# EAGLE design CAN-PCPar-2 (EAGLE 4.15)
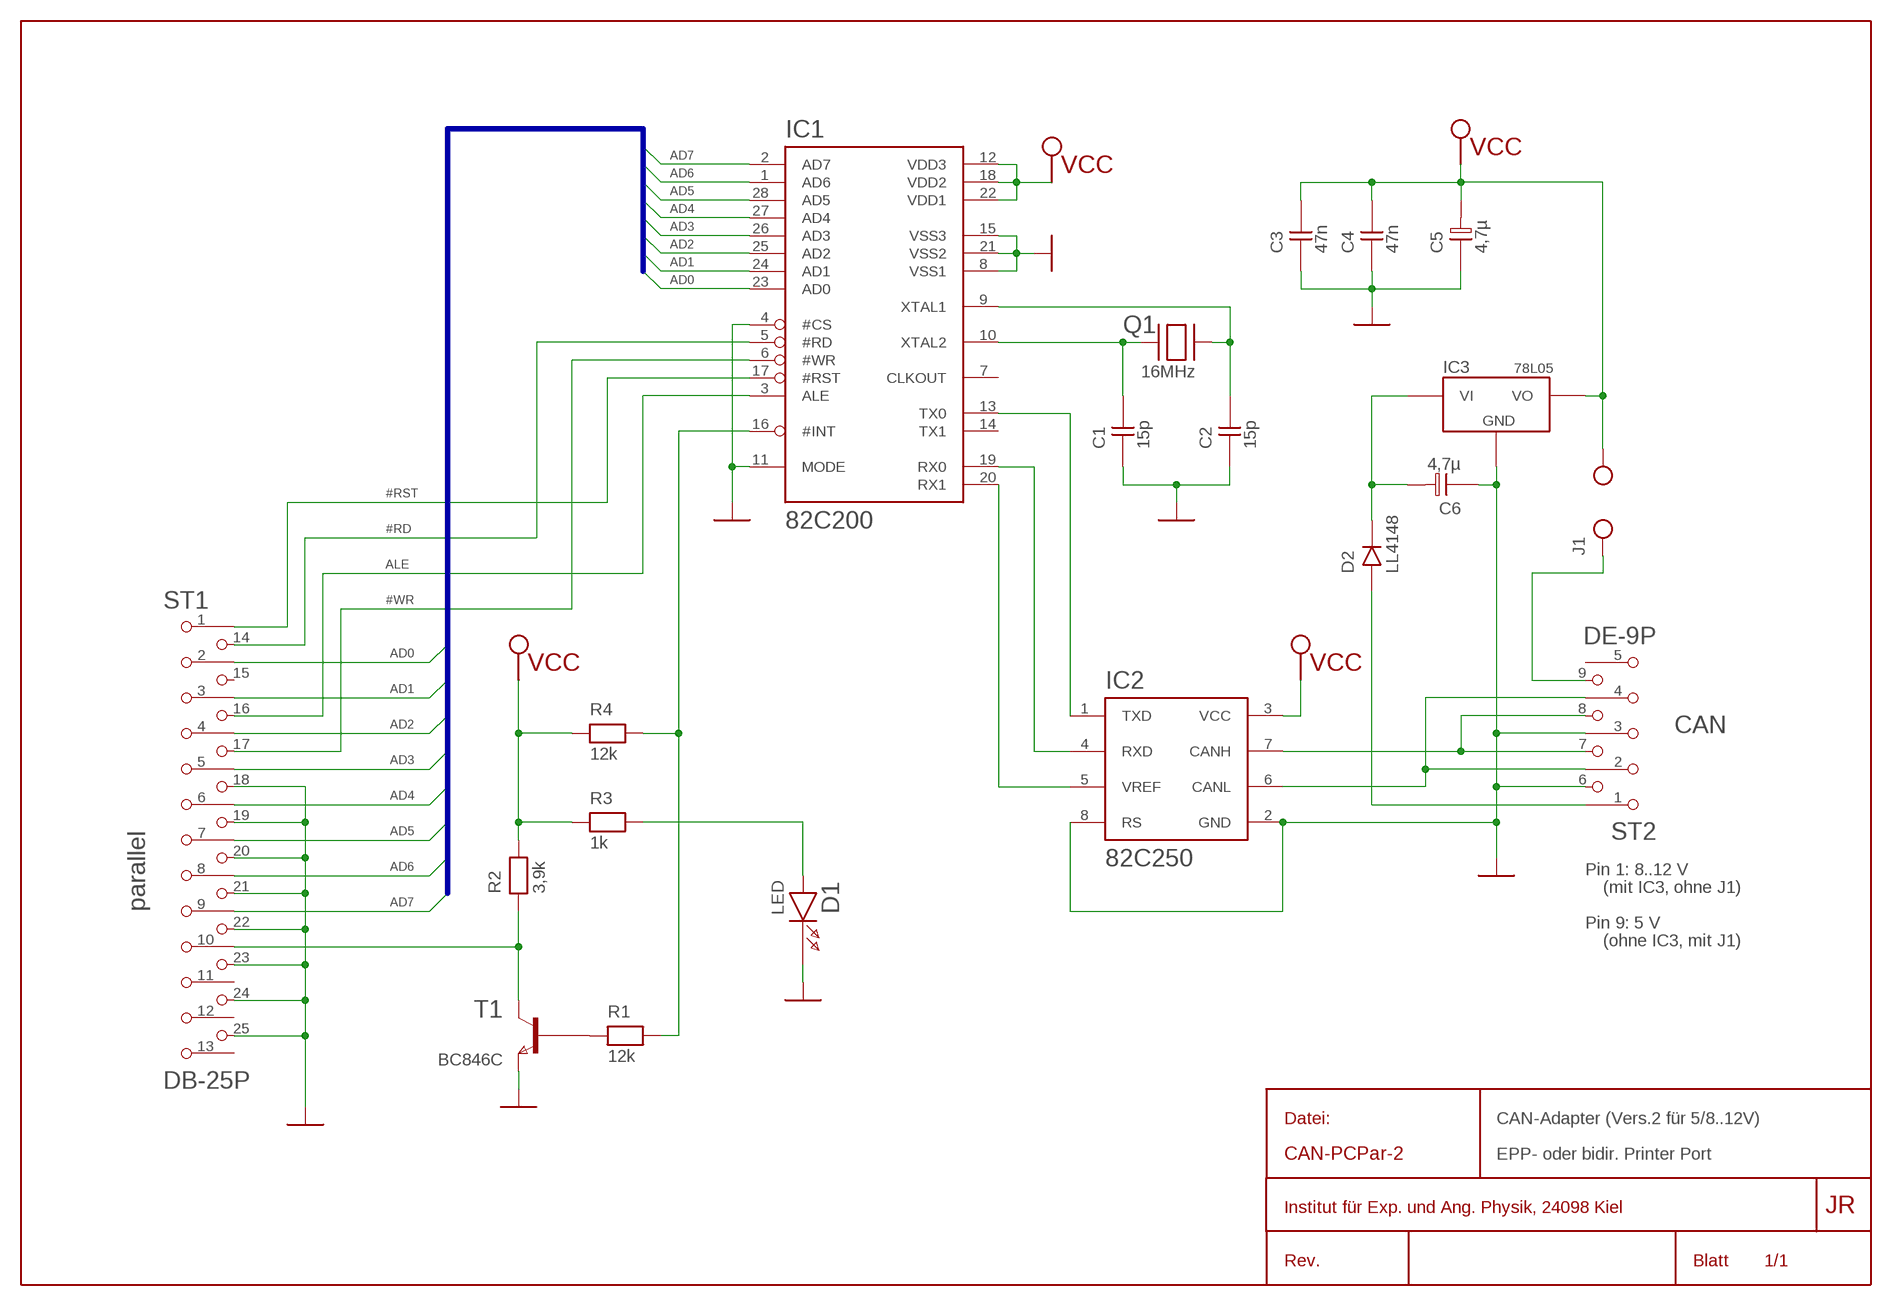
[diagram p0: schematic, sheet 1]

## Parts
C1  15p  CAP01  [C-1206]
C2  15p  CAP01  [C-1206]
C3  47n  CAP02  [C-1206]
C4  47n  CAP02  [C-1206]
C5  4,7µ  ELKOS-3528-B  [E-3528]
C6  4,7µ  ELKOS-3528-B  [E-3528]
D1  LED  [XLED3]
D2  LL4148  D-SOD80  [SOD-80]
IC1  82C200  [SO-28L]
IC2  82C250  [SO-8]
IC3  78L05  78XXTO92-DLH  [XTO92H]
J1  JUMPERSMD  [1206]
Q1  16MHz  QUARZ-V  [XQV]
R1  12k  RES04  [1206]
R2  3,9k  RES04  [1206]
R3  1k  RES04  [1206]
R4  12k  RES03  [1206]
ST1  DB-25P  [D-25ME]
ST2  DE-9P  [D-09ME]
T1  BC846C  NPN-EBC-42  [SOT-23]

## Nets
#RD: IC1.5(#RD) ST1.14
#RST: IC1.17(#RST) ST1.1
#WR: IC1.6(#WR) ST1.17
AD0: IC1.23(AD0) ST1.2
AD1: IC1.24(AD1) ST1.3
AD2: IC1.25(AD2) ST1.4
AD3: IC1.26(AD3) ST1.5
AD4: IC1.27(AD4) ST1.6
AD5: IC1.28(AD5) ST1.7
AD6: IC1.1(AD6) ST1.8
AD7: IC1.2(AD7) ST1.9
ALE: IC1.3(ALE) ST1.16
GND: C1.1 C2.1 C3.1 C4.1 C5.N C6.N D1.K IC1.4(#CS) IC1.8(VSS1) IC1.11(MODE) IC1.15(VSS3) IC1.21(VSS2) IC2.2(GND) IC2.8(RS) IC3.2(GND) ST1.18 ST1.19 ST1.20 ST1.21 ST1.22 ST1.23 ST1.24 ST1.25 ST2.3 ST2.6 T1.1(E)
N$1: C1.2 IC1.10(XTAL2) Q1.1
N$2: C2.2 IC1.9(XTAL1) Q1.2
N$3: R1.1 T1.2(B)
N$4: IC1.16(#INT) R1.2 R4.2
N$5: D1.A R3.2
N$6: J1.1 ST2.9
N$7: C6.P D2.2(K) IC3.3(VI)
N$8: D2.1(A) ST2.1
N$14: IC2.6(CANL) ST2.2 ST2.4
N$16: IC2.7(CANH) ST2.7 ST2.8
N$19: IC1.13(TX0) IC2.1(TXD)
N$20: IC1.19(RX0) IC2.4(RXD)
N$21: IC1.20(RX1) IC2.5(VREF)
N$26: R2.1 ST1.10 T1.3(C)
VCC: C3.2 C4.2 C5.P IC1.12(VDD3) IC1.18(VDD2) IC1.22(VDD1) IC2.3(VCC) IC3.1(VO) J1.2 R2.2 R3.1 R4.1
Unconnected: IC1.7(CLKOUT) IC1.14(TX1) ST1.11 ST1.12 ST1.13 ST1.15 ST2.5

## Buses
AD[0..7]

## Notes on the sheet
- CAN
- Pin 1: 8..12 V
- (mit IC3, ohne J1)
- parallel
- Pin 9: 5 V
- (ohne IC3, mit J1)
- CAN-Adapter (Vers.2 für 5/8..12V)
- EPP- oder bidir. Printer Port

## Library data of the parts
C1 C2 = IAP:CAP01
C3 C4 = IAP:CAP02
C5 C6 = JR:ELKO
D1 = JR:LED
D2 = JR-SMD:D-SOD80
IC1 = CAN:82C200
IC2 = CAN:82C250
IC3 = JR:78XX
J1 = mc-parts:JUMPER: Jumper
Q1 = IAP:QUARZ-V
R1 R2 = IAP:RES04
R3 = JR:RES04
R4 = JR:RES03
ST1 = STECKER:DB-25P
ST2 = STECKER:DE-9P
T1 = IAP:NPN-EBC-42

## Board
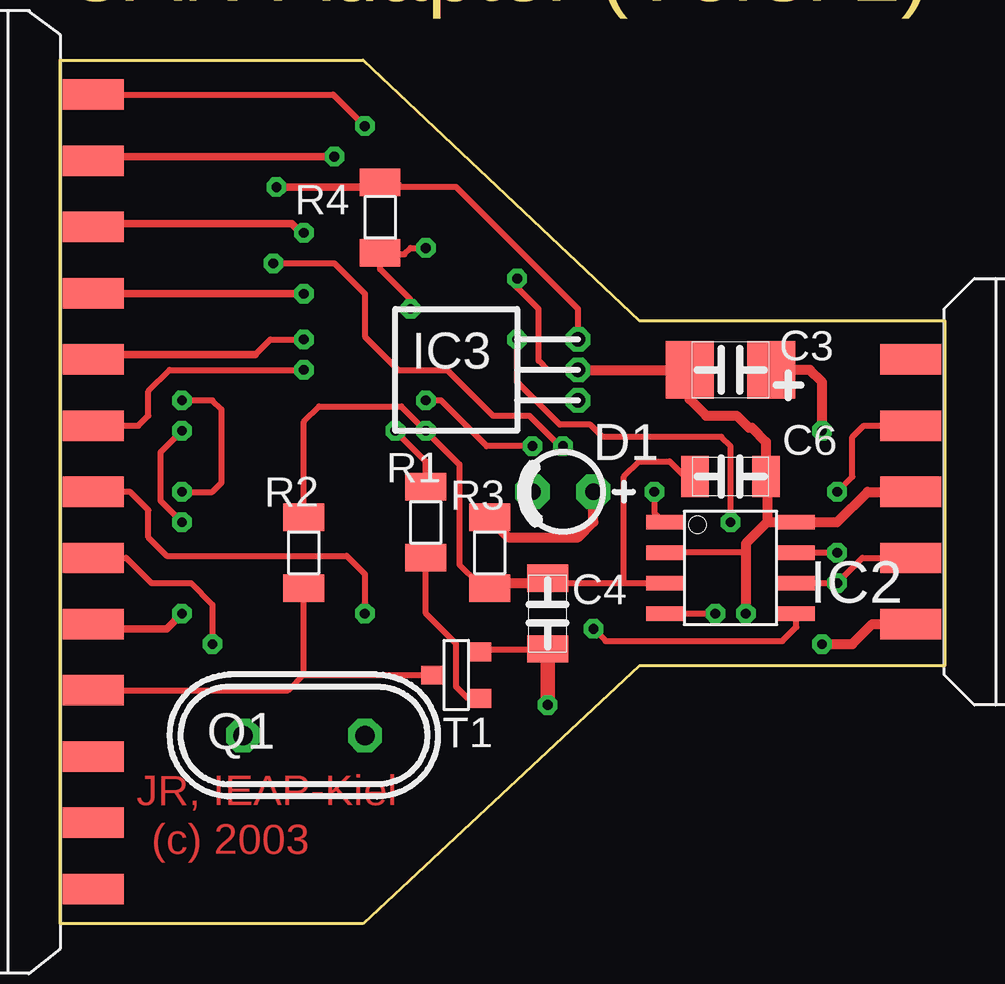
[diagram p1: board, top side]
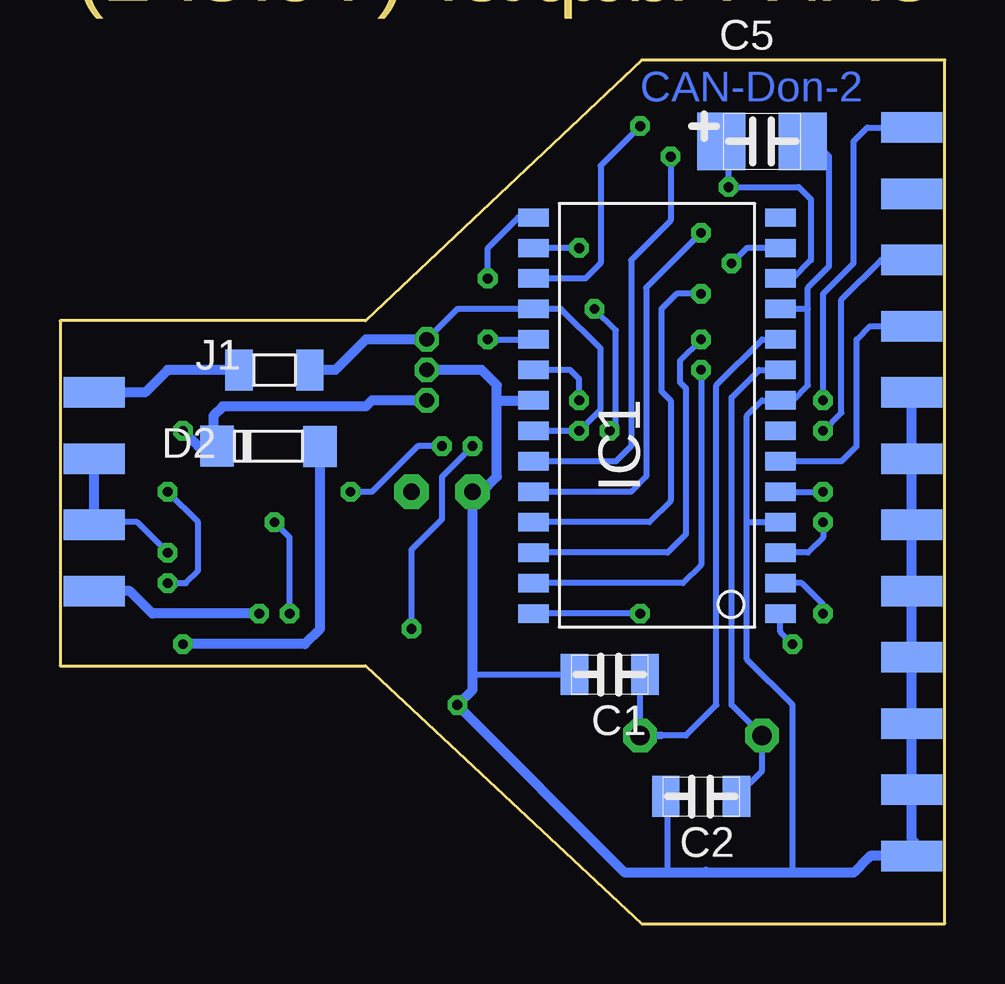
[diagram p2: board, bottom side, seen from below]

Size 36.87 x 36 mm. Coordinates in mm from the lower left corner, seen from the top.
Outline: 0,36 12.63,36 24.14,25.13 36.87,25.13 36.87,10.75 24.14,10.75 12.63,0 0,0 0,36
Copper layers (1*16): Top 0.035mm / dielectric 1.5mm / Bottom 0.035mm
Design rules "Standard": minimum track width 10mil, minimum drill 16mil, track to track 8mil, track to pad 8mil, pad to pad 8mil, via to via 8mil, smd to smd 8mil, copper to edge 0mil, drill to drill 8mil, minimum pad ring 8mil, minimum via ring 8mil, stop-mask expansion 4mil, vias tented up to drill 0mil, thermal gap 10mil

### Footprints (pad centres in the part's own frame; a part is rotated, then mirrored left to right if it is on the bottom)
C-1206 = smd 1.143 x 1.702: 1 -1.473,0; 2 1.473,0
E-3528 = smd 2.007 x 2.388: N 1.702,0; P -1.702,0
XLED3 = drill 0.7 pad 1.422 octagon: A 1.905,0; K -0.635,0
SOD-80 = smd 1.397 x 1.702: 1 1.905,-0.025; 2 -2.388,0
SO-28L = smd 0.762 x 1.27: 1 -7.62,-5.207; 2 -6.35,-5.207; 3 -5.08,-5.207; 4 -3.81,-5.207; 5 -2.54,-5.207; 6 -1.27,-5.207; 7 0,-5.207; 8 1.27,-5.207; 9 2.54,-5.207; 10 3.81,-5.207; 11 5.08,-5.207; 12 6.35,-5.207; 13 7.62,-5.207; 14 8.89,-5.207; 15 8.89,5.08; 16 7.62,5.08; 17 6.35,5.08; 18 5.08,5.08; 19 3.81,5.08; 20 2.54,5.08; 21 1.27,5.08; 22 0,5.08; 23 -1.27,5.08; 24 -2.54,5.08; 25 -3.81,5.08; 26 -5.08,5.08; 27 -6.35,5.08; 28 -7.62,5.08
SO-8 = smd 0.61 x 1.524: 1 -1.27,-2.743; 2 0,-2.743; 3 1.27,-2.743; 4 2.54,-2.743; 5 2.54,2.743; 6 1.27,2.743; 7 0,2.743; 8 -1.27,2.743
XTO92H = drill 0.61 pad 1.016 octagon: 1 -1.27,0; 2 0,0; 3 1.27,0
1206 = smd 1.143 x 1.702: 1 -1.473,0; 2 1.473,0
XQV = drill 0.813 pad 1.397 octagon: 1 0,0; 2 5.08,0
1206@1 = smd 1.143 x 1.702: 1 -1.473,0; 2 1.473,0
D-25ME = smd 1.27 x 2.54: 1 16.56,-1.38; 2 13.8,-1.38; 3 11.04,-1.38; 4 8.28,-1.38; 5 5.52,-1.38; 6 2.76,-1.38; 7 0,-1.38; 8 -2.76,-1.38; 9 -5.52,-1.38; 10 -8.28,-1.38; 11 -11.04,-1.38; 12 -13.8,-1.38; 13 -16.56,-1.38 | smd 1.27 x 2.54 bottom: 14 15.18,-1.38; 15 12.42,-1.38; 16 9.66,-1.38; 17 6.9,-1.38; 18 4.14,-1.38; 19 1.38,-1.38; 20 -1.38,-1.38; 21 -4.14,-1.38; 22 -6.9,-1.38; 23 -9.66,-1.38; 24 -12.42,-1.38; 25 -15.18,-1.38
D-09ME = smd 1.27 x 2.54: 1 5.52,-1.38; 2 2.76,-1.38; 3 0,-1.38; 4 -2.76,-1.38; 5 -5.52,-1.38 | smd 1.27 x 2.54 bottom: 6 4.14,-1.38; 7 1.38,-1.38; 8 -1.38,-1.38; 9 -4.14,-1.38
SOT-23@1 = smd 0.787 x 0.889: 1 -0.94,1.016; 2 0.991,1.016; 3 0.025,-1.016

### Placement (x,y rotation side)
C1  13.97,10.38 0 bottom
C2  10.16,5.3 0 bottom
C3  27.94,18.63 180 top
C4  20.32,12.92 90 top
C5  7.62,32.6 0 bottom
C6  27.94,23.08 180 top
D1  20.32,18 0 top
D2  27.94,19.9 0 bottom
IC1  12.06,20.54 90 bottom
IC2  27.94,15.46 270 top
IC3  21.59,23.08 270 top
J1  27.94,23.08 0 bottom
Q1  12.7,7.84 180 top
R1  12k  [1206@1]  15.24,16.73 90 top
R2  3,9k  [1206@1]  10.16,15.46 90 top
R3  1k  [1206@1]  17.91,15.46 90 top
R4  12k  [1206@1]  13.34,29.43 270 top
ST1  0,18 90 top
ST2  36.83,18 270 top
T1  BC846C  [SOT-23@1]  16.51,10.38 270 top
U$11  [IEAP]  not placed on the board

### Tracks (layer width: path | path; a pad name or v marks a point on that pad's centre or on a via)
#RD  (via drill 0.41 pad 0.81)
  Top 0.254: v5.08,18 6.35,18 6.73,18.38 6.73,21.43 6.35,21.81 v5.08,21.81
  Bottom 0.254: ST1.14 3.23,33.18 3.81,32.6 3.81,27.52 5.08,26.25 v5.08,21.81 | 6.35,18 IC1.5 v5.08,18
#RST  (via drill 0.41 pad 0.81)
  Top 0.254: ST1.1 11.38,34.56 v12.7,33.24
  Bottom 0.254: v12.7,33.24 14.35,31.59 14.35,27.52 14.99,26.89 IC1.17
#WR
  Bottom 0.254: ST1.17 3.13,24.9 3.68,24.35 3.68,19.9 4.32,19.27 IC1.6 6.35,19.27
AD0  (via drill 0.41 pad 0.81)
  Top 0.305: 1.35,31.8 1.27,31.72 | ST1.2 1.35,31.8 | v11.43,31.97 1.52,31.97 1.35,31.8
  Bottom 0.254: v11.43,31.97 11.43,29.3 13.08,27.65 13.08,19.9 13.72,19.27 IC1.23
AD1  (via drill 0.41 pad 0.81)
  Top 0.305: v10.16,28.79 10.03,28.79 9.65,29.18 1.4,29.18 1.27,29.05 1.28,29.04 ST1.3
  Bottom 0.254: v10.16,28.79 12.45,26.51 12.45,18.63 13.08,18 IC1.24
AD2  (via drill 0.41 pad 0.81)
  Top 0.305: ST1.4 1.27,26.38 | ST1.4 | v10.16,26.25 1.4,26.25 ST1.4
  Bottom 0.254: v10.16,26.25 11.18,26.25 11.81,25.62 11.81,22.19 11.43,21.81 11.43,17.62 12.32,16.73 IC1.25
AD3  (via drill 0.41 pad 0.81)
  Top 0.254: 8.13,23.71 8.76,24.35 v10.16,24.35
  Top 0.305: ST1.5 1.38,23.48 1.4,23.46 1.65,23.71 8.13,23.71
  Bottom 0.254: v10.16,24.35 11.05,23.46 11.05,22.57 10.79,22.32 10.79,16.22 11.56,15.46 IC1.26
AD4  (via drill 0.41 pad 0.81)
  Top 0.254: ST1.6 3.27,20.76 3.68,21.17 3.68,22.19 4.57,23.08 v10.16,23.08
  Bottom 0.254: v10.16,23.08 10.16,14.95 10.92,14.19 IC1.27
AD5  (via drill 0.41 pad 0.81)
  Top 0.254: ST1.7 2.92,18 3.68,17.24 3.68,16.09 4.45,15.33 11.94,15.33 12.7,14.57 v12.7,12.92
  Bottom 0.254: v12.7,12.92 IC1.28
AD6  (via drill 0.41 pad 0.81)
  Top 0.254: v6.35,11.65 6.35,13.3 5.46,14.19 3.81,14.19 2.76,15.24 ST1.8
  Bottom 0.254: v6.35,11.65 6.86,12.16 IC1.1
AD7  (via drill 0.41 pad 0.81)
  Top 0.305: ST1.9 1.38,12.52 1.4,12.54 1.65,12.29 4.45,12.29 v5.08,12.92
  Bottom 0.254: v5.08,12.92 5.08,13.3 5.97,14.19 IC1.2
ALE  (via drill 0.41 pad 0.81)
  Top 0.254: v5.08,16.73 4.19,17.62 4.19,19.65 v5.08,20.54
  Bottom 0.254: ST1.16 2.66,27.66 4.32,26 4.32,21.3 v5.08,20.54 | 6.35,15.46 IC1.3 5.71,15.46 5.08,16.09 v5.08,16.73
GND  (via drill 0.41 pad 0.81)
  Top 0.254: 28.57,15.46 IC2.2 | v19.05,26.89 19.05,26.51 19.94,25.62 19.94,23.46 20.32,23.08 IC3.2 | 29.46,18.63 29.46,18.38 | T1.1 17.6,11.4 20.32,11.4
  Top 0.406: ST2.3 33.66,18 32.38,16.73 IC2.8 29.46,16.73 | v28.57,12.92 28.57,15.46 28.57,15.84 29.46,16.73 | 29.46,18.63 C3.1 29.41,20.08 28.83,20.67 28.7,20.67 28.19,21.17 26.92,21.17 26.24,21.86 C6.N IC3.2 | 29.46,18.38 29.46,16.73
  Top 0.61: v20.32,9.11 20.32,11.4 C4.1
  Bottom 0.254: 5.71,25.62 5.71,26.51 4.83,27.4 4.83,31.97 5.46,32.6 C5.N | 6.35,25.62 IC1.11 5.71,25.62 | 5.71,25.62 5.71,22.45 6.35,21.81 IC1.8 7.62,21.81 8.26,21.17 8.26,16.73 | 6.35,16.73 IC1.4 8.26,16.73 | 1.27,2.76 3.17,2.76 | 8.26,16.73 8.26,11.02 6.35,9.11 6.35,2.12 | IC1.15 17.78,29.43 19.05,28.16 v19.05,26.89 | 19.68,10.38 C1.1 | C2.1 11.56,5.22 11.56,2.12
  Bottom 0.305: v28.57,12.92 28.45,12.92
  Bottom 0.406: ST1.19 ST1.18 1.38,16.84 | ST1.19 1.27,19.27 | 1.38,16.84 ST1.19 | ST1.21 ST1.20 1.27,16.73 1.38,16.84 | ST1.21 1.38,13.67 1.27,13.56 | 1.35,11.1 1.27,11.02 | 1.35,11.1 ST1.22 1.38,8.59 1.27,8.48 1.38,8.37 ST1.23 ST1.24 | ST1.21 1.38,11.12 1.35,11.1 | ST1.24 1.38,5.41 1.27,5.3 | ST1.24 1.38,3.51 1.27,3.4 1.27,2.76 1.33,2.82 ST1.25 3.12,2.82 3.17,2.76 3.81,2.12 6.35,2.12 9.91,2.12 | 9.91,2.12 11.56,2.12 13.34,2.12 v20.32,9.11 19.68,9.75 19.68,10.38 D1.K 19.3,18 18.67,18.63 18.67,21.81 | 9.91,2.12 9.96,2.18 | 18.67,21.81 18.67,22.45 19.3,23.08 IC3.2 | 18.67,21.81 IC1.21 | ST2.6 33.96,13.86 33.02,12.92 v28.57,12.92
N$1
  Bottom 0.254: IC1.10 7.62,24.35 9.53,22.45 9.53,9.11 10.79,7.84 Q1.1 12.7,10.18 C1.2
  Bottom 0.305: Q1.1 11.81,7.84
N$2
  Bottom 0.254: IC1.9 7.75,23.08 8.89,21.94 8.89,9.11 Q1.2 7.62,6.37 C2.2
N$3
  Top 0.254: R1.1 15.24,12.92 16.51,11.65 16.51,9.87 16.99,9.39 T1.2
N$4  (via drill 0.41 pad 0.81)
  Top 0.254: v15.24,28.16 14.61,28.16 14.35,27.91 13.46,27.91 13.34,28.03 R4.2 13.34,27.27 14.61,26 v14.61,25.62 | R1.2 15.24,19.27 v13.97,20.54
  Bottom 0.254: v15.24,28.16 IC1.16 | v13.97,20.54 13.72,20.79 13.72,24.73 v14.61,25.62
N$5
  Top 0.406: D1.A 22.23,16.73 21.59,16.09 18.67,16.09 17.91,16.86 R3.2
N$6
  Bottom 0.406: J1.1 29.34,23.08 | ST2.9 33.33,22.14 32.38,23.08 J1.1 | J1.1 29.21,23.08
N$7  (via drill 0.41 pad 0.81)
  Top 0.406: C6.P 31.24,23.08 31.75,22.57 v31.75,20.54
  Bottom 0.406: 30.48,19.9 D2.2 | 30.48,19.9 31.11,19.9 v31.75,20.54 | IC3.3 23.88,21.81 24.13,21.56 30.1,21.56 30.48,21.17 30.48,19.9
N$8  (via drill 0.41 pad 0.81)
  Top 0.406: v31.75,11.65 33.02,11.65 33.85,12.48 ST2.1
  Bottom 0.406: D2.1 26.04,12.29 26.67,11.65 v31.75,11.65
N$14  (via drill 0.41 pad 0.81)
  Top 0.254: ST2.2 33.44,15.24 v32.38,14.19 IC2.6 | ST2.4 33.49,20.76 33.02,20.29 33.02,18.63 v32.38,18
  Bottom 0.254: v32.38,18 31.11,16.73 31.11,14.7 31.62,14.19 v32.38,14.19
N$16  (via drill 0.41 pad 0.81)
  Top 0.254: IC2.7 v32.38,15.46
  Bottom 0.254: v32.38,15.46 33.66,16.73 35.56,16.73 ST2.7
  Bottom 0.406: ST2.8 ST2.7 35.43,16.6
N$19  (via drill 0.41 pad 0.81)
  Top 0.254: v8.89,27.52 11.43,27.52 12.7,26.25 12.7,24.48 14.1,23.08 16.13,23.08 18.03,21.17 19.56,21.17 20.83,19.9 v20.95,19.9 | IC2.1 25.15,16.73 24.77,17.11 v24.77,18
  Bottom 0.254: IC1.13 8.26,28.16 v8.89,27.52 | v24.77,18 23.88,18 21.97,19.9 v20.95,19.9
N$20  (via drill 0.41 pad 0.81)
  Top 0.254: v19.05,24.35 19.05,22.57 20.83,20.79 22.1,20.79 22.61,20.29 27.56,20.29 27.94,19.9 v27.94,16.73 | 25.15,12.92 IC2.4 v27.3,12.92
  Bottom 0.254: v19.05,24.35 IC1.19 | v27.3,12.92 27.3,16.09 v27.94,16.73
N$21  (via drill 0.41 pad 0.81)
  Top 0.254: IC2.5 30.68,12.36 30.1,11.78 22.73,11.78 v22.23,12.29 | v19.68,19.9 17.78,19.9 15.88,21.81 v15.24,21.81
  Bottom 0.254: v22.23,12.29 22.23,15.59 20.95,16.86 20.95,18.63 v19.68,19.9 | v15.24,21.81 15.24,22.7 15.62,23.08 17.02,23.08 17.14,22.95 IC1.20
N$26
  Top 0.254: ST1.10 9.5,9.72 10.16,10.38 | 10.16,10.38 R2.1 | T1.3 10.19,10.36 10.16,10.38
VCC  (via drill 0.41 pad 0.81)
  Top 0.254: C4.2 20.32,14.19 23.5,14.19 | 23.5,14.19 IC2.3 | C3.2 26.04,18.63 25.4,19.27 24.13,19.27 23.5,18.63 23.5,14.19 | R4.1 14.02,30.9 14.22,30.7 16.51,30.7 21.59,25.62 IC3.1 | R2.2 10.24,16.93 10.29,16.98 10.16,17.11 10.16,20.92 10.79,21.56 14.22,21.56 v15.24,20.54 16.64,19.14 16.64,14.95 17.4,14.19 18.03,14.19
  Top 0.305: R4.1 13.28,30.9 13.08,30.7 v9.02,30.7
  Top 0.406: R3.1 17.91,14.06 18.03,14.19 20.32,14.19
  Bottom 0.254: IC1.12 6.35,26.89 5.59,27.65 5.59,30.19 6.1,30.7 v9.02,30.7 9.02,31.46 | IC1.22 v15.24,20.54 14.35,21.43 14.35,23.97 16,25.62 IC1.18 20.32,25.62 IC3.1 | 9.02,31.46 9.09,31.54 | C5.P 9.32,31.77 9.02,31.46
  Bottom 0.406: J1.2 25.4,23.08 24.13,24.35 IC3.1

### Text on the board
Top: JR, IEAP-Kiel | (c) 2003
Bottom: CAN-Don-2
Dimension: CAN-Adapter (Vers. 2) | (Rev. A)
